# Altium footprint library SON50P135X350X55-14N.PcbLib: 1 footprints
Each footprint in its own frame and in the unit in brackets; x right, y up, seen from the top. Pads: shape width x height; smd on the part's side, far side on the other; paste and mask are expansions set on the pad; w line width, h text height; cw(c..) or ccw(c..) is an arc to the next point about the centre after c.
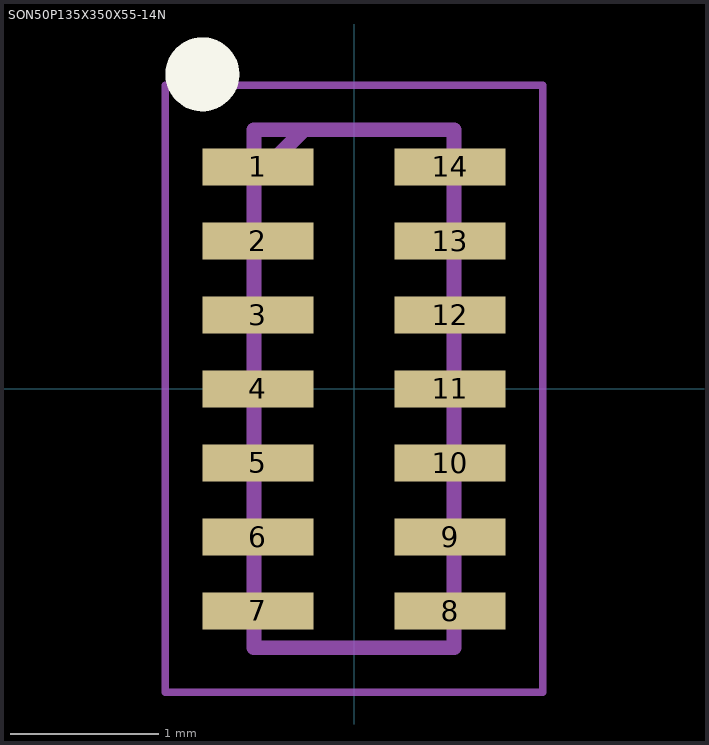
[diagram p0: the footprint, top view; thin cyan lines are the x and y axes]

## SON50P135X350X55-14N [mm]
pads (14):
  rect 0.75x0.25 smd: 1(-0.65,1.5) 2(-0.65,1) 3(-0.65,0.5) 4(-0.65,0) 5(-0.65,-0.5) 6(-0.65,-1) 7(-0.65,-1.5) 8(0.65,-1.5) 9(0.65,-1) 10(0.65,-0.5) 11(0.65,0) 12(0.65,0.5) 13(0.65,1) 14(0.65,1.5)
Top Overlay:
  circle w0.25: c-1.025,2.125 r0.125
Mechanical 15:
  lines w0.1: -0.675,1.412 -0.338,1.75 ; -0.675,-1.75 0.675,-1.75 0.675,1.75 -0.675,1.75 -0.675,-1.75
Mechanical 20:
  lines w0.05: -1.275,-2.05 1.275,-2.05 1.275,2.05 -1.275,2.05 -1.275,-2.05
